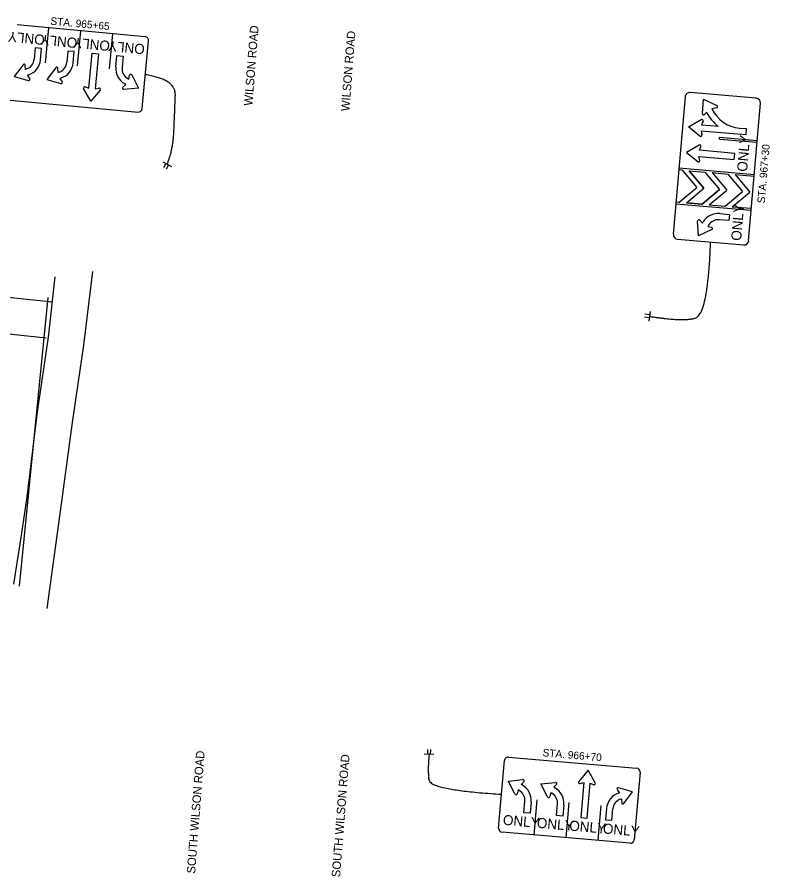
# Model space of a CAD drawing. Extents: x 1847379 to 1850904, y 217032 to 220169.
# Drawn here: x 1850655.3 to 1850904.1, y 218559.4 to 218843.8 of the extents above; entities that cross this region are included whole.
import ezdxf

# ---------------------------------------------------------------- set-up
doc = ezdxf.new("R2010")
doc.units = 0
for name, color, linetype in [('BR_P_Gen_Phase_Construction', 7, 'Continuous'), ('PM_P_Crosswalk', 7, 'Continuous'), ('PM_P_Edge_Line', 7, 'Continuous'), ('PM_P_Lane_Line', 7, 'Continuous'), ('SN_X_Public', 7, 'Continuous')]:
    doc.layers.add(name, color=color, linetype=linetype)

msp = doc.modelspace()

# ---------------------------------------------------------------- linework, layer by layer
at = {"layer": 'BR_P_Gen_Phase_Construction'}
msp.add_line((1850665.4, 218751.05), (1850656, 218655.59), dxfattribs=at)
at = {"layer": 'PM_P_Crosswalk'}
for points in [[(1850654.2, 218656.28), (1850656.83, 218673.13), (1850658.58, 218685.16), (1850662.02, 218713.29), (1850665.61, 218737.95), (1850667.89, 218757.85)], [(1850665.24, 218648.21), (1850669.77, 218681.15), (1850673.63, 218709.77), (1850677.32, 218735.26), (1850680.31, 218759.64)]]:
    msp.add_lwpolyline(points, dxfattribs=at)
at = {"layer": 'PM_P_Edge_Line'}
msp.add_lwpolyline([(1849889.22, 218821.46), (1849908.57, 218819.63), (1849959.34, 218815.75), (1850016.54, 218811.11), (1850069.2, 218806.62), (1850120.11, 218802.11), (1850169.53, 218797.86), (1850218.84, 218793.6), (1850268.16, 218788.98), (1850318.46, 218784.1), (1850367.53, 218779.29), (1850417.75, 218774.53), (1850467.84, 218769.49), (1850519.01, 218764.5), (1850567.74, 218759.83), (1850617.52, 218754.84), (1850666.94, 218749.6)], dxfattribs=at)
at = {"layer": 'PM_P_Lane_Line'}
msp.add_lwpolyline([(1849608.99, 218828.81), (1849660.31, 218825.18), (1849710.18, 218821.58), (1849761.09, 218817.87), (1849808.06, 218814.41), (1849858.45, 218811.1), (1849907.69, 218807.67), (1849958.4, 218803.79), (1850015.55, 218799.15), (1850068.16, 218794.66), (1850119.07, 218790.16), (1850168.5, 218785.91), (1850217.76, 218781.65), (1850267.02, 218777.03), (1850317.3, 218772.15), (1850366.38, 218767.35), (1850416.59, 218762.59), (1850466.65, 218757.55), (1850517.86, 218752.55), (1850566.57, 218747.88), (1850616.29, 218742.91), (1850664.9, 218737.75)], dxfattribs=at)
at = {"layer": 'SN_X_Public'}
for p, q in [((1850664.69, 218828.68), (1850665.78, 218840.3)), ((1850675.26, 218827.69), (1850676.35, 218839.3)), ((1850685.83, 218826.7), (1850686.92, 218838.31)), ((1850661.28, 218833.6), (1850660.93, 218829.87)), ((1850663.36, 218833.41), (1850661.28, 218833.6)), ((1850663.01, 218829.67), (1850663.36, 218833.41)), ((1850672.07, 218832.59), (1850671.72, 218828.86)), ((1850674.14, 218832.4), (1850672.07, 218832.59)), ((1850673.79, 218828.66), (1850674.14, 218832.4)), ((1850678.98, 218820.29), (1850680.06, 218831.84)), ((1850680.06, 218831.84), (1850682.14, 218831.65)), ((1850682.14, 218831.65), (1850681.06, 218820.1)), ((1850687.9, 218827.34), (1850688.25, 218831.07)), ((1850688.25, 218831.07), (1850690.32, 218830.88)), ((1850690.32, 218830.88), (1850689.97, 218827.15)), ((1850657.25, 218828.07), (1850654.34, 218824.21)), ((1850658.02, 218826.54), (1850657.99, 218827.83)), ((1850658.39, 218826.66), (1850658.02, 218826.54)), ((1850668.03, 218827.06), (1850665.12, 218823.2)), ((1850668.81, 218825.53), (1850668.78, 218826.82)), ((1850669.17, 218825.65), (1850668.81, 218825.53)), ((1850654.34, 218824.21), (1850658.98, 218822.87)), ((1850658.68, 218824.56), (1850659.05, 218824.69)), ((1850659.43, 218823.52), (1850658.68, 218824.56)), ((1850665.12, 218823.2), (1850669.77, 218821.86)), ((1850669.47, 218823.55), (1850669.83, 218823.67)), ((1850670.22, 218822.51), (1850669.47, 218823.55)), ((1850691.88, 218823.52), (1850692.22, 218823.33)), ((1850692.22, 218823.33), (1850692.48, 218824.59)), ((1850693.26, 218824.69), (1850695.4, 218820.36)), ((1850679.62, 218815.98), (1850677.27, 218820.2)), ((1850677.79, 218820.79), (1850678.98, 218820.29)), ((1850681.06, 218820.1), (1850682.32, 218820.36)), ((1850690.27, 218820.63), (1850691.2, 218821.51)), ((1850695.4, 218820.36), (1850690.59, 218819.91)), ((1850691.2, 218821.51), (1850690.86, 218821.7)), ((1850682.72, 218819.69), (1850679.62, 218815.98)), ((1850881.84, 218811.89), (1850882.25, 218816.71)), ((1850882.25, 218816.71), (1850886.6, 218814.59)), ((1850883.26, 218812.32), (1850882.56, 218811.57)), ((1850886.51, 218813.81), (1850885.01, 218813.49)), ((1850877.28, 218807.52), (1850881.49, 218809.9)), ((1850882.08, 218809.38), (1850881.59, 218808.19)), ((1850881.02, 218804.45), (1850877.28, 218807.52)), ((1850896.19, 218804.84), (1850881.41, 218806.12)), ((1850881.41, 218806.12), (1850881.69, 218804.86)), ((1850881.59, 218808.19), (1850887.02, 218807.72)), ((1850894.09, 218807.12), (1850896.37, 218806.92)), ((1850896.37, 218806.92), (1850896.19, 218804.84)), ((1850887.49, 218803.47), (1850887.54, 218804.09)), ((1850887.49, 218803.47), (1850887.54, 218804.09)), ((1850887.49, 218803.47), (1850899.94, 218802.4)), ((1850887.49, 218803.47), (1850899.94, 218802.4)), ((1850887.54, 218804.09), (1850900, 218803.02)), ((1850887.54, 218804.09), (1850900, 218803.02)), ((1850880.76, 218801.46), (1850876.56, 218799.07)), ((1850880.86, 218799.75), (1850881.35, 218800.94)), ((1850876.56, 218799.07), (1850880.29, 218796)), ((1850880.96, 218796.41), (1850880.68, 218797.67)), ((1850880.68, 218797.67), (1850892.34, 218796.67)), ((1850892.52, 218798.74), (1850880.86, 218799.75)), ((1850892.34, 218796.67), (1850892.52, 218798.74)), ((1850703.46, 218795.94), (1850706.29, 218794.43)), ((1850704.45, 218795.41), (1850703.7, 218794)), ((1850705.3, 218794.96), (1850704.54, 218793.55)), ((1850704.88, 218795.18), (1850704.88, 218795.18)), ((1850875.11, 218793.23), (1850874.07, 218793.32)), ((1850874.12, 218793.94), (1850899.03, 218791.79)), ((1850875.11, 218793.23), (1850879.95, 218787.47)), ((1850877.46, 218793.02), (1850882.3, 218787.27)), ((1850877.46, 218793.02), (1850882.7, 218792.57)), ((1850882.3, 218787.27), (1850877.46, 218793.02)), ((1850877.46, 218793.02), (1850882.7, 218792.57)), ((1850882.7, 218792.57), (1850887.54, 218786.82)), ((1850882.7, 218792.57), (1850887.54, 218786.82)), ((1850885.05, 218792.37), (1850889.89, 218786.61)), ((1850885.05, 218792.37), (1850890.29, 218791.92)), ((1850890.29, 218791.92), (1850895.13, 218786.16)), ((1850892.64, 218791.72), (1850897.48, 218785.96)), ((1850892.64, 218791.72), (1850898.98, 218791.17)), ((1850874.19, 218782.62), (1850879.95, 218787.47)), ((1850876.54, 218782.42), (1850882.3, 218787.27)), ((1850876.54, 218782.42), (1850882.3, 218787.27)), ((1850881.79, 218781.97), (1850887.54, 218786.82)), ((1850887.54, 218786.82), (1850881.79, 218781.97)), ((1850884.13, 218781.77), (1850889.89, 218786.61)), ((1850889.38, 218781.32), (1850895.13, 218786.16)), ((1850891.72, 218781.11), (1850897.48, 218785.96)), ((1850873.1, 218782.09), (1850898.01, 218779.95)), ((1850873.16, 218782.71), (1850874.19, 218782.62)), ((1850876.54, 218782.42), (1850881.79, 218781.97)), ((1850881.79, 218781.97), (1850876.54, 218782.42)), ((1850884.13, 218781.77), (1850889.38, 218781.32)), ((1850891.72, 218781.11), (1850898.06, 218780.57)), ((1850887.56, 218778.85), (1850890.78, 218778.57)), ((1850890.78, 218778.57), (1850890.6, 218776.49)), ((1850880.55, 218771.5), (1850880.26, 218776.33)), ((1850880.99, 218776.63), (1850881.84, 218775.67)), ((1850881.84, 218775.67), (1850882.07, 218776.04)), ((1850883.85, 218774.97), (1850883.63, 218774.6)), ((1850883.63, 218774.6), (1850884.88, 218774.29)), ((1850890.6, 218776.49), (1850887.39, 218776.77)), ((1850884.95, 218773.51), (1850880.55, 218771.5)), ((1850864.57, 218746.42), (1850864.18, 218743.25)), ((1850864.32, 218744.36), (1850862.73, 218744.55)), ((1850864.44, 218745.31), (1850862.85, 218745.51)), ((1850864.38, 218744.83), (1850864.38, 218744.83)), ((1850791.02, 218600), (1850791.07, 218601.6)), ((1850791.98, 218599.98), (1850792.03, 218601.57)), ((1850793.1, 218599.94), (1850789.9, 218600.04)), ((1850791.5, 218599.99), (1850791.5, 218599.99)), ((1850844.04, 218594.72), (1850840.97, 218590.99)), ((1850846.43, 218590.52), (1850844.04, 218594.72)), ((1850817.69, 218591.13), (1850822.5, 218591.62)), ((1850819.87, 218586.82), (1850817.69, 218591.13)), ((1850822.83, 218590.9), (1850821.9, 218590.01)), ((1850821.9, 218590.01), (1850822.24, 218589.82)), ((1850828.48, 218590.2), (1850833.29, 218590.69)), ((1850830.66, 218585.89), (1850828.48, 218590.2)), ((1850833.62, 218589.97), (1850832.7, 218589.08)), ((1850841.38, 218590.31), (1850842.64, 218590.59)), ((1850842.64, 218590.59), (1850841.65, 218579.03)), ((1850843.72, 218578.85), (1850844.72, 218590.41)), ((1850844.72, 218590.41), (1850845.91, 218589.92)), ((1850820.9, 218588.18), (1850820.65, 218586.92)), ((1850821.24, 218588), (1850820.9, 218588.18)), ((1850831.69, 218587.25), (1850831.44, 218585.99)), ((1850832.03, 218587.07), (1850831.69, 218587.25)), ((1850832.7, 218589.08), (1850833.04, 218588.89)), ((1850853.69, 218588.25), (1850854.45, 218587.21)), ((1850854.45, 218587.21), (1850854.08, 218587.08)), ((1850858.79, 218587.59), (1850854.13, 218588.9)), ((1850855.91, 218583.71), (1850858.79, 218587.59)), ((1850822.85, 218580.65), (1850823.17, 218584.39)), ((1850825.25, 218584.21), (1850824.93, 218580.47)), ((1850827.08, 218584.89), (1850826.08, 218573.26)), ((1850837.66, 218583.98), (1850836.66, 218572.35)), ((1850854.75, 218585.11), (1850855.12, 218585.24)), ((1850855.12, 218585.24), (1850855.16, 218583.95)), ((1850833.65, 218579.72), (1850833.97, 218583.46)), ((1850836.04, 218583.28), (1850835.72, 218579.54)), ((1850848.24, 218583.07), (1850847.24, 218571.44)), ((1850850.16, 218582.06), (1850849.84, 218578.33)), ((1850851.91, 218578.15), (1850852.23, 218581.89)), ((1850824.93, 218580.47), (1850822.85, 218580.65)), ((1850835.72, 218579.54), (1850833.65, 218579.72)), ((1850841.65, 218579.03), (1850843.72, 218578.85)), ((1850849.84, 218578.33), (1850851.91, 218578.15))]:
    msp.add_line(p, q, dxfattribs=at)
for points in [[(1850697.62, 218837.31), (1850655.31, 218841.28)], [(1850696.65, 218813.55), (1850698.75, 218835.95)], [(1850876.15, 218817.45), (1850872.23, 218772.01)], [(1850899.63, 218816.99), (1850877.84, 218818.87)], [(1850652.97, 218816.39), (1850695.29, 218812.42)], [(1850897.14, 218769.86), (1850901.05, 218815.3)], [(1850873.66, 218770.32), (1850895.45, 218768.44)], [(1850817.75, 218599.07), (1850860.09, 218595.43)], [(1850814.46, 218575.52), (1850816.39, 218597.94)], [(1850861.23, 218594.08), (1850859.3, 218571.66)], [(1850857.95, 218570.52), (1850815.6, 218574.17)]]:
    msp.add_lwpolyline(points, dxfattribs=at)
for centre, radius, start, end in [((1850697.51, 218836.06), 1.25, 354.6423, 84.6423), ((1850657.2, 218830.22), 3.75, 288.4655, 354.6423), ((1850657.2, 218830.22), 5.83, 288.4655, 354.6423), ((1850667.99, 218829.21), 3.75, 288.4655, 354.6423), ((1850667.99, 218829.21), 5.83, 288.4655, 354.6423), ((1850657.58, 218827.82), 0.417, 1.1037, 142.9818), ((1850668.36, 218826.81), 0.417, 1.1037, 142.9818), ((1850693.71, 218826.8), 5.83, 174.6423, 240.8191), ((1850693.71, 218826.8), 3.75, 174.6423, 240.8191), ((1850659.1, 218823.27), 0.417, 253.9492, 35.8273), ((1850692.89, 218824.51), 0.417, 26.3028, 168.1809), ((1850669.88, 218822.26), 0.417, 253.9492, 35.8273), ((1850677.63, 218820.4), 0.417, 67.2805, 209.1586), ((1850682.4, 218819.96), 0.417, 320.126, 102.0041), ((1850690.55, 218820.32), 0.417, 133.4573, 275.3354), ((1850877.7, 218817.31), 1.56, 85.0783, 175.0783), ((1850886.42, 218814.22), 0.417, 282.193, 64.0711), ((1850899.5, 218815.44), 1.56, 355.0783, 85.0783), ((1850695.4, 218813.66), 1.25, 264.6423, 354.6423), ((1850882.25, 218811.86), 0.417, 175.0386, 316.9167), ((1850895.03, 218818.12), 13.13, 206.2107, 232.3532), ((1850895.03, 218818.12), 11.04, 204.7867, 265.0783), ((1850881.69, 218809.54), 0.417, 337.7165, 119.5946), ((1850881.28, 218804.77), 0.417, 230.5621, 12.4402), ((1850880.96, 218801.1), 0.417, 337.7165, 119.5946), ((1850880.55, 218796.32), 0.417, 230.5621, 12.4402), ((1850887.06, 218773.03), 5.83, 85.0783, 149.0603), ((1850880.67, 218776.35), 0.417, 41.6409, 183.519), ((1850887.06, 218773.03), 3.75, 85.0783, 149.0745), ((1850873.79, 218771.87), 1.56, 175.0783, 265.0783), ((1850884.78, 218773.89), 0.417, 294.4865, 76.3646), ((1850895.59, 218770), 1.56, 265.0783, 355.0783), ((1850817.64, 218597.83), 1.25, 85.0783, 175.0783), ((1850859.98, 218594.18), 1.25, 355.0783, 85.0783), ((1850819.44, 218584.71), 5.83, 355.0783, 61.2551), ((1850822.54, 218591.2), 0.417, 313.8933, 95.7714), ((1850833.34, 218590.27), 0.417, 313.8933, 95.7714), ((1850841.29, 218590.72), 0.417, 140.5621, 282.4402), ((1850846.07, 218590.31), 0.417, 247.7165, 29.5946), ((1850820.24, 218587), 0.417, 206.7389, 348.617), ((1850819.44, 218584.71), 3.75, 355.0783, 61.2551), ((1850830.23, 218583.78), 3.75, 355.0783, 61.2551), ((1850830.23, 218583.78), 5.83, 355.0783, 61.2551), ((1850855.97, 218581.56), 5.83, 108.9015, 175.0783), ((1850854.02, 218588.49), 0.417, 74.3853, 216.2634), ((1850831.03, 218586.07), 0.417, 206.7389, 348.617), ((1850855.97, 218581.56), 3.75, 108.9015, 175.0783), ((1850855.57, 218583.96), 0.417, 181.5397, 323.4178), ((1850815.71, 218575.41), 1.25, 175.0783, 265.0783), ((1850858.05, 218571.77), 1.25, 265.0783, 355.0783)]:
    msp.add_arc(centre, radius, start, end, dxfattribs=at)
for points in [[(1850704.88, 218795.18), (1850706.87, 218799.87), (1850707.4, 218812.74), (1850707.8, 218823.21), (1850697.7, 218824.75)], [(1850864.38, 218744.83), (1850875.02, 218743.1), (1850883.71, 218745.3), (1850884.55, 218769.38)], [(1850791.5, 218599.99), (1850790.93, 218594.5), (1850792.02, 218588.23), (1850815.43, 218586.73)]]:
    msp.add_open_spline(points, degree=2, dxfattribs=at)

# ---------------------------------------------------------------- texts
for s, height, rotation, p in [('STA. 965+65', 2.5, 354.6423, (1850666.21, 218841.33)), ('WILSON ROAD', 2.8, 85.5355, (1850733.06, 218814.41)), ('ONLY', 3.333, 174.6423, (1850664.55, 218837.9)), ('ONLY', 3.333, 174.6423, (1850675.29, 218836.89)), ('WILSON ROAD', 2.8, 85.5355, (1850765.11, 218812.61)), ('ONLY', 3.333, 174.6423, (1850686.1, 218835.88)), ('ONLY', 3.333, 174.6423, (1850697.62, 218834.8)), ('ONLY', 3.333, 85.0783, (1850896.59, 218792.56)), ('STA. 967+30', 2.5, 85.0783, (1850902.46, 218782.13)), ('ONLY', 3.333, 85.0783, (1850894.62, 218769.72)), ('SOUTH WILSON ROAD', 2.8, 85.5355, (1850714.13, 218560.42)), ('STA. 966+70', 2.5, 355.0783, (1850828.93, 218599.33)), ('SOUTH WILSON ROAD', 2.8, 85.5355, (1850762.04, 218559.22)), ('ONLY', 3.333, 355.0783, (1850815.79, 218576.66)), ('ONLY', 3.333, 355.0783, (1850827.01, 218575.69)), ('ONLY', 3.333, 355.0783, (1850837.72, 218574.77)), ('ONLY', 3.333, 355.0783, (1850848.84, 218573.81))]:
    msp.add_text(s, height=height, rotation=rotation, dxfattribs=at).set_placement(p)

doc.saveas('drawing.dxf')
